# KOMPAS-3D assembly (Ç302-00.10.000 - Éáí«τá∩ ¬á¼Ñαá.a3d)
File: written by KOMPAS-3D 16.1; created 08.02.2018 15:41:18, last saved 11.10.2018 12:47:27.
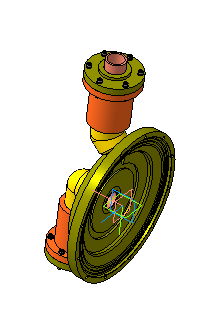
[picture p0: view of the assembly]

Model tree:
1. Массив по образцу:1  (6 pattern instances)
2. Массив по образцу:2  (6 pattern instances)
3. Сечение поверхностью:1  (labels: А302-00.10.000; C:\Program Files\ASCON\KOMPAS-3D V16\Sys\bo_atr.lat; SYSTEM_PROPERTY_ADDITIONAL_FOR:5.000000)
     Расстояние = 13; Расстояние = -13; Расстояние = 1.65; Расстояние = 1.65; Расстояние = -2.4; Расстояние = 2.4

Expressions: A2-70; М5 x 35 - A2-70
Referenced files in Z:\Мембранные насосы\Мембранный электропривод\А302-00.00.000 - ASTRA-302 (МЭ200)\3Д\: А302-00.11.000 - Крышка рабочей камеры.a3d, А302-00.10.001 - Седло.m3d, А302-00.10.002 3Д - Стакан.m3d, А302-00.30.000 - Прижим.a3d
Referenced files in Z:\1 ПКИ 3D\2 Китай\: Шар PTFE ф45.m3d
Referenced files in C:\Program Files\ASCON\KOMPAS-3D V16\Libs\PartLib\DATA\vault\Methods\Kompas\3D\: PLib_Washer_1_712.m3d, PLib_Screw_DIN_7984_1500.m3d
Referenced files in C:\Program Files\ASCON\KOMPAS-3D V16\Libs\PartLib\DATA\VAULT\Methods\kompas\3d\: PLib_Washer_2_712.m3d
Referenced files in Z:\2 Стандартные изделия 3D\Гайки\DIN 6927\: Гайка шестигранная самостопорящаяся с фланцем DIN 6927-M5 - A2-70.m3d
Referenced files in Z:\1 ПКИ 3D\РТИ\Кольца ГОСТ 9833-76\: Кольцо 054-058-25 EPDM ГОСТ 9833-76.m3d, Кольцо 058-062-25 EPDM ГОСТ 9833-76.m3d
Referenced files in Z:\Мембранные насосы\Мембранный электропривод\А302-00.00.000 - ASTRA-302 (МЭ200)\Чертежи\: А302-00.11.000 - Крышка рабочей камеры.cdw, А302-00.10.001 - Седло.cdw, А302-00.30.000 - Прижим.cdw
Referenced files: GRAPHIC.TDP
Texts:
  Крышка рабочей камеры
  для мембранного насоса
  Шар @2~45mm PTFE / для мембранного насоса
  Сталь 12Х18Н10Т ГОСТ 5632-72
  Шайба C.5.21 ГОСТ 11371-78
  Крепежное изделие ГОСТ
  Сталь 30Х13 ГОСТ 5632-72
  Шайба 5 30Х13 ГОСТ 6402-70
  Гайка шестигранная самостопорящаяся с фланцем
  DIN 6927-M5-A2-70
  Винт с цилиндрической головкой и шестигранным углублением под ключ ГОСТ Р ИСО 4762 - М5 x 35 - A2-70
  Винт с цилиндрической головкой и
  шестигранным углублением под ключ
  ГОСТ Р ИСО  4762-М5 x 35-A2-70
  Винт с цилиндрической головкой и шестигранным углублением под ключ
  Винт с цилиндрической головкой и шестигранным углублением под ключ ГОСТ Р ИСО  4762-М5 x 35-A2-70
  Винт с цилиндрической головкой и шестигранным углублением под ключ ГОСТ Р ИСО 4762 - М5 x 40 - A2-70
  Кольцо 054-058-25
  материал EPDM ГОСТ 9833-76
  Кольцо 054-058-25 / материал EPDM ГОСТ 9833-76
  Кольцо 058-062-25
  Кольцо 058-062-25 / материал EPDM ГОСТ 9833-76
  ГОСТ 11371-78
  ГОСТ 6402-70
  ГОСТ Р ИСО 4762-2012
